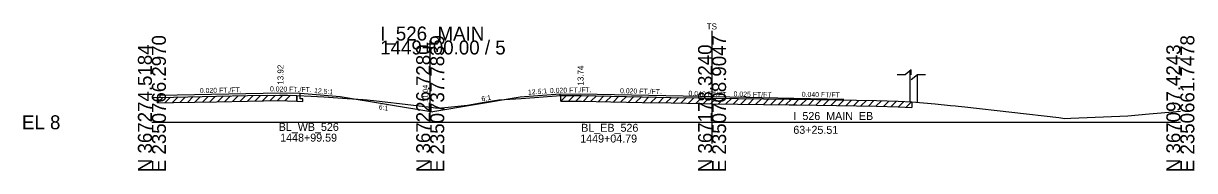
# Model space of a CAD drawing. Extents: x -170 to 2527928, y -10 to 1619750.
# Drawn here: x 4974.3 to 5208.5, y 8990.3 to 9019.8 of the extents above; entities that cross this region are included whole.
import ezdxf

# ---------------------------------------------------------------- set-up
doc = ezdxf.new("R2010")
doc.units = 0
for name, color, linetype in [('Default', 7, 'Continuous'), ('RD_GPK_XS_Cell', 7, 'Continuous'), ('RD_PD_NOISE-WALL-GM', 7, 'Continuous'), ('RD_XS_Base', 7, 'Continuous'), ('RD_XS_EarthShd', 7, 'Continuous'), ('RD_XS_ExGround', 7, 'Continuous'), ('RD_XS_ExPaveRet', 7, 'Continuous'), ('RD_XS_MatchLine', 7, 'Continuous'), ('RD_XS_Pave', 7, 'Continuous'), ('RD_XS_PaveShd', 7, 'Continuous'), ('RD_XS_TieSlope', 7, 'Continuous'), ('RD_XS_TX_Elev_EX', 7, 'Continuous'), ('RD_XS_TX_Slope', 7, 'Continuous'), ('RD_XS_TX_Station', 7, 'Continuous')]:
    doc.layers.add(name, color=color, linetype=linetype)

msp = doc.modelspace()

# ---------------------------------------------------------------- linework, layer by layer
at = {"layer": 'Default'}
for p, q in [((5150.59, 9009.52), (5149.01, 9009.52)), ((5151.84, 9010.55), (5150.59, 9009.52)), ((5151.84, 9009.52), (5151.84, 9010.55)), ((5153.09, 9009.52), (5151.84, 9008.5)), ((5154.69, 9009.52), (5153.09, 9009.52))]:
    msp.add_line(p, q, dxfattribs=at)
at = {"layer": 'RD_GPK_XS_Cell'}
for p, q in [((5055.65, 9000), (5055.65, 9016.4)), ((5000, 9000), (5055.65, 9000)), ((5055.65, 9000), (5112.01, 9000)), ((5112.01, 9000), (5205.65, 9000))]:
    msp.add_line(p, q, dxfattribs=at)
at = {"layer": 'RD_PD_NOISE-WALL-GM'}
for p, q in [((5151.59, 9004.14), (5151.59, 9010.34)), ((5153.09, 9004.02), (5153.09, 9009.52))]:
    msp.add_line(p, q, dxfattribs=at)
at = {"layer": 'RD_XS_Base'}
for p, q in [((5028.97, 9004.22), (5028.97, 9005.37)), ((5029.65, 9004.7), (5029.65, 9005.84)), ((5030.15, 9004.69), (5029.65, 9004.7)), ((5030.15, 9004.19), (5030.15, 9004.69)), ((5081.65, 9005.35), (5081.65, 9005.66)), ((5028.97, 9004.22), (5030.15, 9004.19))]:
    msp.add_line(p, q, dxfattribs=at)
at = {"layer": 'RD_XS_EarthShd'}
for p, q in [((5029.65, 9005.84), (5037.65, 9005.2)), ((5081.65, 9005.66), (5073.65, 9005.02))]:
    msp.add_line(p, q, dxfattribs=at)
at = {"layer": 'RD_XS_ExGround'}
msp.add_lwpolyline([(5000, 9004.98), (5000.31, 9004.99), (5000.53, 9005), (5004.29, 9005.07), (5012.9, 9005.23), (5019.09, 9005.35), (5025.49, 9005.47), (5027.13, 9005.42), (5028.97, 9005.37), (5031.86, 9005.22), (5034.37, 9005.12), (5039.04, 9004.79), (5042.24, 9004.56), (5043.05, 9004.5), (5044.92, 9004.29), (5051.77, 9003.5), (5055.68, 9003.03), (5057.21, 9002.85), (5059.9, 9003.1), (5063.13, 9003.46), (5066.42, 9004.04), (5069.4, 9004.49), (5073.82, 9004.79), (5081.79, 9005.35), (5083.05, 9005.36), (5085.9, 9005.38), (5091.74, 9005.25), (5098.01, 9005.11), (5103.81, 9005), (5110.06, 9004.88), (5112.01, 9004.85), (5127.4, 9004.65), (5128.28, 9004.64), (5128.9, 9004.63), (5144.91, 9004.34), (5149.24, 9004.21), (5151.98, 9004.13), (5156.62, 9003.68), (5159.72, 9003.38), (5160.72, 9003.28), (5161.19, 9003.24), (5162.53, 9003.11), (5181.33, 9000.99), (5182.58, 9000.75), (5183.77, 9000.82), (5195.17, 9001.27), (5199.41, 9001.67), (5200.99, 9001.8), (5205.65, 9002.22)], dxfattribs=at)
at = {"layer": 'RD_XS_ExPaveRet'}
for p, q in [((5001.1, 9003.89), (5002.24, 9005.03)), ((5001.1, 9003.89), (5001.1, 9005.01)), ((5002.6, 9003.91), (5003.74, 9005.06)), ((5004.1, 9003.94), (5005.24, 9005.09)), ((5005.6, 9003.97), (5006.74, 9005.12)), ((5007.1, 9004), (5008.24, 9005.14)), ((5008.6, 9004.03), (5009.74, 9005.17)), ((5010.1, 9004.06), (5011.24, 9005.2)), ((5011.6, 9004.09), (5012.74, 9005.23)), ((5013.1, 9004.11), (5014.24, 9005.26)), ((5014.6, 9004.14), (5015.74, 9005.28)), ((5016.1, 9004.17), (5017.24, 9005.31)), ((5017.6, 9004.2), (5018.74, 9005.34)), ((5019.1, 9004.23), (5020.24, 9005.37)), ((5020.6, 9004.25), (5021.74, 9005.4)), ((5022.1, 9004.28), (5023.24, 9005.42)), ((5023.6, 9004.31), (5024.74, 9005.45)), ((5025.1, 9004.34), (5026.21, 9005.45)), ((5026.6, 9004.32), (5027.69, 9005.41)), ((5028.97, 9005.37), (5028.97, 9004.25)), ((5081.79, 9004.23), (5082.92, 9005.36)), ((5081.79, 9004.23), (5081.79, 9005.35)), ((5083.29, 9004.24), (5084.42, 9005.37)), ((5084.79, 9004.25), (5085.91, 9005.38)), ((5086.29, 9004.25), (5087.38, 9005.35)), ((5087.79, 9004.22), (5088.88, 9005.32)), ((5089.29, 9004.19), (5090.38, 9005.28)), ((5090.79, 9004.15), (5091.88, 9005.25)), ((5092.29, 9004.12), (5093.38, 9005.22)), ((5093.79, 9004.09), (5094.88, 9005.18)), ((5095.29, 9004.05), (5096.38, 9005.15)), ((5096.79, 9004.02), (5097.88, 9005.11)), ((5098.29, 9003.98), (5099.39, 9005.08)), ((5099.79, 9003.96), (5100.89, 9005.05)), ((5101.29, 9003.93), (5102.39, 9005.02)), ((5102.79, 9003.9), (5103.89, 9004.99)), ((5104.29, 9003.87), (5105.39, 9004.97)), ((5105.79, 9003.84), (5106.89, 9004.94)), ((5107.29, 9003.81), (5108.39, 9004.91)), ((5108.79, 9003.78), (5109.89, 9004.88)), ((5110.29, 9003.76), (5111.39, 9004.86)), ((5111.79, 9003.74), (5112.89, 9004.84)), ((5113.29, 9003.72), (5114.39, 9004.82)), ((5114.79, 9003.7), (5115.89, 9004.8)), ((5116.29, 9003.68), (5117.39, 9004.78)), ((5117.79, 9003.66), (5118.89, 9004.76)), ((5119.29, 9003.64), (5120.39, 9004.74)), ((5120.79, 9003.62), (5121.89, 9004.73)), ((5122.29, 9003.6), (5123.39, 9004.71)), ((5123.79, 9003.58), (5124.89, 9004.69)), ((5125.29, 9003.56), (5126.39, 9004.67)), ((5126.79, 9003.54), (5127.89, 9004.65)), ((5128.29, 9003.52), (5129.39, 9004.62)), ((5129.79, 9003.49), (5130.89, 9004.59)), ((5131.29, 9003.46), (5132.39, 9004.57)), ((5132.79, 9003.44), (5133.89, 9004.54)), ((5134.29, 9003.41), (5135.39, 9004.51)), ((5001.1, 9003.89), (5004.29, 9003.95)), ((5004.29, 9003.95), (5012.9, 9004.11)), ((5012.9, 9004.11), (5019.09, 9004.23)), ((5019.09, 9004.23), (5025.49, 9004.35)), ((5025.49, 9004.35), (5027.13, 9004.3)), ((5027.13, 9004.3), (5028.97, 9004.25)), ((5081.79, 9004.23), (5083.05, 9004.24)), ((5083.05, 9004.24), (5085.9, 9004.26)), ((5085.9, 9004.26), (5091.74, 9004.13)), ((5091.74, 9004.13), (5098.01, 9003.99)), ((5098.01, 9003.99), (5103.81, 9003.87)), ((5103.81, 9003.87), (5110.06, 9003.76)), ((5110.06, 9003.76), (5112.01, 9003.73)), ((5112.01, 9003.73), (5127.4, 9003.53)), ((5127.4, 9003.53), (5128.28, 9003.52)), ((5128.28, 9003.52), (5128.9, 9003.51)), ((5128.9, 9003.51), (5144.91, 9003.21)), ((5135.79, 9003.38), (5136.89, 9004.48)), ((5137.29, 9003.35), (5138.39, 9004.46)), ((5138.79, 9003.33), (5139.89, 9004.43)), ((5140.29, 9003.3), (5141.39, 9004.4)), ((5141.79, 9003.27), (5142.89, 9004.37)), ((5143.29, 9003.24), (5144.39, 9004.34)), ((5144.79, 9003.22), (5145.88, 9004.31)), ((5144.91, 9003.21), (5149.24, 9003.09)), ((5146.29, 9003.17), (5147.37, 9004.26)), ((5147.79, 9003.13), (5148.87, 9004.22)), ((5149.24, 9003.09), (5151.98, 9003)), ((5149.29, 9003.08), (5150.37, 9004.17)), ((5150.79, 9003.04), (5151.87, 9004.13)), ((5151.98, 9004.13), (5151.98, 9003))]:
    msp.add_line(p, q, dxfattribs=at)
at = {"layer": 'RD_XS_MatchLine'}
msp.add_line((5112.02, 8995.76), (5112.02, 9018.35), dxfattribs=at)
at = {"layer": 'RD_XS_Pave'}
for p, q in [((5001.65, 9005.44), (5025.65, 9005.92)), ((5085.65, 9005.74), (5109.65, 9005.26)), ((5112.35, 9005.15), (5128.36, 9004.83))]:
    msp.add_line(p, q, dxfattribs=at)
at = {"layer": 'RD_XS_PaveShd'}
for p, q in [((5001.65, 9005.02), (5001.65, 9005.44)), ((5025.65, 9005.92), (5029.65, 9005.84)), ((5081.65, 9005.66), (5085.65, 9005.74)), ((5109.65, 9005.26), (5112.35, 9005.15)), ((5128.36, 9004.83), (5138.37, 9004.65))]:
    msp.add_line(p, q, dxfattribs=at)
at = {"layer": 'RD_XS_TieSlope'}
for p in [(5037.65, 9005.2), (5073.65, 9005.02)]:
    msp.add_line(p, (5056.19, 9002.11), dxfattribs=at)

# ---------------------------------------------------------------- texts
at = {"layer": 'RD_GPK_XS_Cell'}
for s, p in [('I_526_MAIN', (5045.65, 9016.4)), ('1449+00.00 / 5', (5045.65, 9013.6)), ('EL 8', (4974, 8998.6))]:
    msp.add_text(s, height=2.8, dxfattribs=at).set_placement(p)
for s, p in [('E 2350766.2970', (5002.8, 8990)), ('E 2350737.7839', (5058.45, 8990)), ('E 2350708.9047', (5114.81, 8990)), ('E 2350661.7478', (5208.45, 8990)), ('N 367274.5184', (5000, 8990)), ('N 367226.7280', (5055.65, 8990)), ('N 367178.3240', (5112.01, 8990)), ('N 367097.4243', (5205.65, 8990))]:
    msp.add_text(s, height=2.8, rotation=90, dxfattribs=at).set_placement(p)
at = {"layer": 'RD_XS_MatchLine'}
msp.add_text('TS', height=1.2, dxfattribs=at).set_placement((5110.94, 9018.62))
at = {"layer": 'RD_XS_TX_Elev_EX'}
msp.add_text('11.04', height=1, rotation=90, dxfattribs=at).set_placement((5055.15, 9004.04))
at = {"layer": 'RD_XS_TX_Slope'}
for s, rotation, p in [('0.020 FT./FT.', 1.1458, (5009.59, 9005.85)), ('0.020 FT./FT.', 358.8542, (5023.6, 9006.21)), ('0.020 FT./FT.', 1.1458, (5079.59, 9005.87)), ('12.5:1', 355.4261, (5032.4, 9005.88)), ('6:1', 9.4623, (5065.98, 9004.2)), ('12.5:1', 4.5739, (5075.23, 9005.53)), ('0.020 FT./FT.', 358.8542, (5093.6, 9005.83)), ('0.040 FT/FT', 357.7094, (5107.28, 9005.34)), ('0.025 FT/FT', 358.5427, (5116.3, 9005.2)), ('0.040 FT/FT', 359.1102, (5129.94, 9005.11)), ('6:1', 350.5446, (5045.29, 9002.62))]:
    msp.add_text(s, height=1, rotation=rotation, dxfattribs=at).set_placement(p)
at = {"layer": 'RD_XS_TX_Station'}
for s, p in [(' 13.92', (5026.31, 9007.09)), (' 13.74', (5086.31, 9006.91))]:
    msp.add_text(s, height=1.2, rotation=90, dxfattribs=at).set_placement(p)
for s, p in [('BL_WB_526', (5025.36, 8998.27)), ('I_526_MAIN_EB', (5128.29, 9000.46)), ('1448+99.59', (5025.65, 8996.12)), ('1449+04.79', (5085.65, 8995.94)), ('BL_EB_526', (5085.85, 8998.1)), ('63+25.51', (5128.26, 8997.69))]:
    msp.add_text(s, height=1.6, dxfattribs=at).set_placement(p)

doc.saveas('drawing.dxf')
